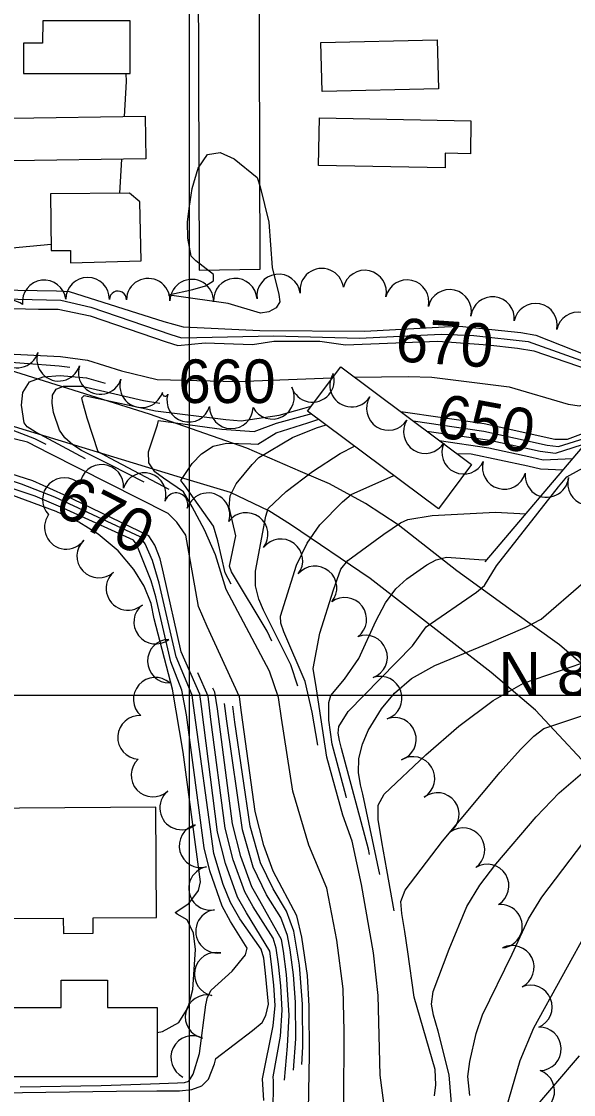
# Model space of a CAD drawing. Extents: x 79600 to 91800, y 75600 to 84400.
# Drawn here: x 84622.9 to 84876.3, y 82816.8 to 83309.4 of the extents above; entities that cross this region are included whole.
import ezdxf

# ---------------------------------------------------------------- set-up
doc = ezdxf.new("R2010")
doc.units = 0
for name, color, linetype in [('084-085$0$BLDG', 7, 'Continuous'), ('084-085$0$GRID', 7, 'Continuous'), ('084-085$0$INDEX', 7, 'Continuous'), ('084-085$0$INDXLBL', 7, 'Continuous'), ('084-085$0$INTER', 7, 'Continuous'), ('084-085$0$ROAD', 7, 'Continuous'), ('084-085$0$TREES', 7, 'Continuous'), ('084-085$0$WALL', 7, 'Continuous'), ('084-090$0$GRID', 7, 'Continuous'), ('084-090$0$TI_BORDER', 7, 'Continuous')]:
    doc.layers.add(name, color=color, linetype=linetype)

msp = doc.modelspace()

# ---------------------------------------------------------------- linework, layer by layer
at = {"layer": '084-085$0$BLDG'}
for points in [[(84632.59, 83299.52), (84623.84, 83299.53), (84623.82, 83285.55), (84672.7, 83285.47), (84672.74, 83309.69), (84632.61, 83309.75)], [(84814.26, 83278.51), (84760.86, 83277.2), (84760.3, 83299.73), (84813.7, 83301.04)], [(84679.96, 83246.32), (84618.56, 83245.4), (84618.27, 83264.98), (84679.67, 83265.9)], [(84828.92, 83248.69), (84817.4, 83248.9), (84817.28, 83242.26), (84759.25, 83243.35), (84759.66, 83265.15), (84829.2, 83263.84)], [(84636.25, 83230.28), (84636.51, 83204.21), (84645.39, 83204.29), (84645.44, 83198.59), (84677.86, 83199.47), (84677.12, 83226.67), (84672.43, 83230.63)], [(84769.42, 83150.92), (84829.42, 83106.08), (84814.23, 83085.75), (84754.23, 83130.59)], [(84580.41, 82897.68), (84604.06, 82897.84), (84604.11, 82890.71), (84617.59, 82890.81), (84617.54, 82897.58), (84642.03, 82897.75), (84642.08, 82890.78), (84655.75, 82890.87), (84655.7, 82897.85), (84684.85, 82898.06), (84684.5, 82948.69), (84580.07, 82947.96)], [(84641.12, 82856.71), (84641.12, 82869.23), (84662.34, 82869.24), (84662.35, 82856.79), (84685.1, 82856.8), (84685.11, 82824.98), (84609.62, 82824.95), (84609.61, 82856.7)]]:
    msp.add_lwpolyline(points, close=True, dxfattribs=at)
at = {"layer": '084-085$0$GRID'}
msp.add_line((85000, 83000), (80000, 83000), dxfattribs=at)
at = {"layer": '084-085$0$INDEX'}
for points in [[(84600.69, 83178.14), (84630.62, 83177.35), (84639.67, 83177.29), (84654.42, 83174.27), (84689.3, 83162.42), (84694.63, 83160.72), (84707.14, 83161.95), (84728.87, 83161.11), (84738.73, 83162.64), (84759.87, 83162.62), (84771.59, 83161), (84814.01, 83162.68), (84836.88, 83160.95), (84850.54, 83159.5), (84858.07, 83158.14), (84887.97, 83147.96)], [(84613.42, 83157.05), (84640.78, 83155.58), (84653.15, 83153.95), (84668.79, 83149.1), (84685.18, 83144.99), (84721.6, 83144.12), (84765.37, 83145.87), (84765.65, 83145.88)], [(84775.93, 83146.06), (84800.37, 83146.48), (84811.16, 83146.11), (84846.77, 83141.61), (84873.75, 83133.74), (84879.07, 83132.94), (84882.6, 83134.05), (84889.03, 83133.81), (84925.64, 83118.29), (84936.16, 83113.35), (84942.47, 83111.34), (84949.29, 83110.42), (84963.52, 83112.56), (84976.14, 83115.96), (84981.44, 83117.59), (84986.28, 83119.78), (85000, 83131.29)], [(84797.03, 83130.29), (84835.27, 83124.87), (84867.74, 83117.7), (84873.5, 83117.68), (84882.14, 83120.89), (84885.57, 83121.36), (84894.14, 83119.08), (84907.07, 83114.28), (84930.3, 83102.42), (84935.65, 83099.95), (84941.32, 83098.68), (84948.66, 83099), (84969.1, 83104.02), (84989.2, 83110.03), (85000, 83117.94)], [(84770.89, 82812.2), (84770.95, 82845.86), (84770.56, 82865.33), (84767.7, 82887.72), (84763.04, 82911.54), (84754.72, 82931.33), (84747.41, 82956.06), (84742.21, 82989.57), (84740.79, 82999.09), (84736.79, 83011.16), (84716.86, 83048.62), (84711.98, 83064.62), (84706.88, 83076.04), (84701.2, 83086.55), (84697.21, 83093.55), (84688.11, 83099.71), (84684.03, 83102.74), (84681.34, 83106.85), (84681.2, 83111.92), (84685.27, 83124.25), (84685.79, 83126.17), (84714.82, 83122.19), (84729.72, 83121.15), (84739.99, 83124.97), (84755.15, 83129.1), (84755.94, 83129.32)], [(84754.44, 82801.21), (84755.14, 82834.95), (84754.98, 82857.36), (84754.16, 82871.43), (84751.62, 82888.97), (84749.33, 82898.8), (84738.41, 82919.37), (84734.16, 82931.14), (84730.15, 82946.66), (84723.88, 82992.22), (84722.87, 82999.42), (84708.08, 83031.7), (84704.11, 83040.89), (84699.29, 83068.36), (84698.3, 83073.53), (84694.25, 83079.59), (84690.23, 83083.46), (84635.72, 83111.09), (84625.56, 83116.31), (84614.94, 83118.89)], [(84734.16, 82814.01), (84733.49, 82824.02), (84738.44, 82848.36), (84739.35, 82857.71), (84738.69, 82867.06), (84737.66, 82876.7), (84736.85, 82882.66), (84726.13, 82900.19), (84722.1, 82907.42), (84716.48, 82922.83), (84712.89, 82937.26), (84705.54, 82994.86), (84704.74, 83000.59), (84696.23, 83020.07), (84688.03, 83056.1), (84686.53, 83062.72), (84684.14, 83069.05), (84681.29, 83073.28), (84642.31, 83092.12), (84628.08, 83098.53), (84618.03, 83101.8)], [(84789.99, 82807.25), (84787.46, 82825.72), (84786.64, 82862.26), (84784.47, 82881.83), (84778.99, 82913.19), (84774.71, 82933.14), (84770.32, 82945.08), (84763.03, 82971.73), (84758.32, 83003.08), (84756.77, 83012.31), (84759.81, 83028.55), (84766.03, 83048.54), (84769.48, 83058), (84772.67, 83061.91), (84789.25, 83074.09), (84796.8, 83079.19), (84800.23, 83080.81), (84811.44, 83082.64), (84840.48, 83084.21), (84854.31, 83083.37)], [(84812.44, 82816.18), (84813.14, 82821.23), (84812.72, 82828.34), (84803.13, 82861.49), (84800.25, 82882.28), (84798.8, 82891.7), (84797.52, 82899.93), (84797.04, 82905.38), (84798.93, 82910.55), (84816.14, 82933.05), (84842.63, 82964.86), (84851.89, 82975.21), (84858.13, 82981.36), (84862.64, 82984.84), (84904.89, 82998.96)]]:
    msp.add_lwpolyline(points, dxfattribs=at)
at = {"layer": '084-085$0$INTER'}
msp.add_line((84668.08, 83230.59), (84668.98, 83246.15), dxfattribs=at)
for points in [[(84670.11, 83265.75), (84671.04, 83281.83), (84670.96, 83285.47)], [(84453.38, 83232.93), (84461.75, 83230.58), (84475.08, 83222.88), (84480.65, 83219.56), (84532.34, 83204.8), (84540.51, 83203.1), (84555.44, 83201.56), (84570.31, 83200.91), (84626.75, 83206.24), (84636.48, 83207.12)], [(84399.8, 83133.35), (84399.48, 83133.66), (84396.09, 83136.82), (84401.25, 83144.46), (84411.96, 83173.61), (84414.41, 83181.53), (84415.26, 83183.72), (84418.13, 83186.19), (84438.41, 83189.33), (84534.13, 83190.88), (84561.82, 83190.24), (84594.28, 83186.5), (84638.9, 83185.76), (84644.74, 83185.39), (84688.16, 83171.72), (84697.11, 83169.26), (84732.33, 83167.57), (84780.5, 83167.18), (84817.11, 83169.16), (84823.94, 83169.5), (84852.04, 83166.65), (84859.01, 83165.47), (84882.18, 83156.19)], [(84436.19, 83127.82), (84428.13, 83136.47), (84427.4, 83147.43), (84427.72, 83154.33), (84430.17, 83166.84), (84433.23, 83177.63), (84435.64, 83180.52), (84442.38, 83182.23), (84528.29, 83186.73), (84549.58, 83186.91), (84594.73, 83182.62), (84640.9, 83181.53), (84654.66, 83178.33), (84691.41, 83165.78), (84696.3, 83164.22), (84738.48, 83165.14), (84777.96, 83163.96), (84815.56, 83165.92), (84830.45, 83165.23), (84855.49, 83162.54), (84888.55, 83150.67)], [(84634.16, 83115.18), (84628.97, 83117.84), (84619.05, 83121.6), (84611.39, 83124.97), (84606.27, 83128.02), (84601.94, 83131.63), (84599.33, 83135.53), (84598.01, 83139.6), (84596.33, 83147.77), (84596.27, 83151.2), (84598.08, 83153.46), (84607.93, 83153.83), (84640.21, 83151.32), (84645.01, 83150.78)], [(84652.25, 83108.68), (84629.17, 83121.01), (84625.54, 83123.26), (84624.03, 83125.18), (84622.95, 83133.31), (84623.53, 83139.15), (84626.54, 83143.95), (84632.78, 83146.35), (84640.63, 83146.86), (84652.77, 83145.81), (84661.34, 83143.43)], [(84679.15, 83097.97), (84663.81, 83105.66), (84650.4, 83112.5), (84646.41, 83115.11), (84642.81, 83118.26), (84640.27, 83121.85), (84637.58, 83129.93), (84636.9, 83134.14), (84637.07, 83137.91), (84638.73, 83140.66), (84642.22, 83142), (84650.63, 83142.03), (84678.91, 83135.44), (84686.39, 83134.13)], [(84690.59, 83094.51), (84663.7, 83108.73), (84658.08, 83111.84), (84652.99, 83127.26), (84650.81, 83135.09), (84650.61, 83136.68), (84651.65, 83137.65), (84684.35, 83130.64), (84716.65, 83126.74), (84723.75, 83126.13), (84741.11, 83128.7), (84752.61, 83131.95), (84755.87, 83132.78)], [(84719.06, 83051.08), (84716.35, 83056.33), (84713, 83071.03), (84711, 83077.66), (84697.72, 83096.56), (84696.05, 83098.63), (84701.29, 83106.45), (84705.52, 83110.9), (84710.88, 83114.39), (84717.05, 83115.87), (84728.19, 83115.5), (84731.38, 83115.44), (84739.82, 83120.51), (84754.28, 83125.17), (84759.29, 83126.81)], [(84802.64, 83126.1), (84835.11, 83121.27), (84864.12, 83114.94), (84869.31, 83114.36), (84881.56, 83118.19), (84884.87, 83118.87), (84892.63, 83117.1), (84910.77, 83110.14), (84930.26, 83099.74), (84935.55, 83097.27), (84941.09, 83096.15), (84948.53, 83096.72), (84970.21, 83102.31), (84986.78, 83107.29), (84993.3, 83109.65), (85000, 83115.27)], [(84737.75, 83024.98), (84735.66, 83029.5), (84719.35, 83056.73), (84718.32, 83059.29), (84721.24, 83073.22), (84718.18, 83086.47), (84718.73, 83091.7), (84721.44, 83097.15), (84728.79, 83106.07), (84731.82, 83109.32), (84747.3, 83118.48), (84758.22, 83122.79), (84762.7, 83124.26)], [(84808.95, 83121.38), (84837.86, 83117.25), (84860.92, 83112.12), (84868.06, 83111.25), (84884.18, 83116.38), (84891.12, 83115.12), (84903.78, 83110.63), (84930.22, 83097.06), (84935.45, 83094.59), (84940.86, 83093.62), (84948.41, 83094.44), (84971.33, 83100.61), (84988.56, 83105.85), (84994.47, 83107.97), (85000, 83112.6)], [(84814.65, 83117.12), (84837.33, 83113.67), (84857.15, 83109.34), (84862.28, 83108.21), (84875.86, 83108.75)], [(84749.75, 83004.27), (84746.5, 83014.08), (84734.02, 83039.2), (84731.79, 83044.19), (84730.32, 83050.26), (84730.27, 83057), (84734.97, 83082.25), (84736.15, 83085.77), (84744.37, 83093.64), (84756.4, 83102.79), (84769.21, 83111.1), (84775.77, 83114.5)], [(84822.77, 83111.05), (84829.24, 83110.98), (84855.34, 83105.47), (84861.06, 83103.99), (84871.51, 83103.63)], [(84758.88, 82977.24), (84756.28, 82992.4), (84753.04, 83006.42), (84743.36, 83029.26), (84741.86, 83033.14), (84741.81, 83036.33), (84749.18, 83059.75), (84754, 83069.96), (84759.8, 83078.37), (84770.29, 83088.91), (84774.23, 83092.22), (84793.78, 83101.03)], [(84782.67, 82926.95), (84782.22, 82929.37), (84769.83, 82975.6), (84768.83, 82979.29), (84768.21, 82982.69), (84768.6, 82985.77), (84772.79, 82992.66), (84802.33, 83022.85), (84808.69, 83031.44), (84831.71, 83047.45), (84835.35, 83050.47), (84840.88, 83059.54), (84869.41, 83095.73), (84873.16, 83100.34), (84879.09, 83103.64), (84882.22, 83105.24), (84889.67, 83103.56), (84903.38, 83098.11), (84930.01, 83083.64), (84934.88, 83081.17), (84939.17, 83080.79), (84982.25, 83093.32), (85000, 83096.88)], [(84612.32, 82817.59), (84666.43, 82818.35), (84684.97, 82818.46), (84695.46, 82818.55), (84701.01, 82819.09), (84705.66, 82820.77), (84708.75, 82823.92), (84711.42, 82830.88), (84712.03, 82833.39), (84728.84, 82846.26), (84733.37, 82849.86), (84735.1, 82853.08), (84736.24, 82858.36), (84734.95, 82872.45), (84734.16, 82879.47), (84732.88, 82883.52), (84723.08, 82897.43), (84718.83, 82905.02), (84715.43, 82913.28), (84711.24, 82927.5), (84701.88, 82995.39), (84701.29, 83000.17), (84693.86, 83017.75), (84686.11, 83051.53), (84682.95, 83061.9), (84679.59, 83069.62), (84677.42, 83072.79), (84638.12, 83091.02), (84622.92, 83097.03), (84617.89, 83098.63)], [(84622.32, 82820.34), (84659.51, 82821.01), (84682.13, 82821.69), (84694.54, 82822.1), (84697.75, 82822.35), (84699.68, 82823), (84701.71, 82826.18), (84704.63, 82835.7), (84707.54, 82857.99), (84708.25, 82861.51), (84709.88, 82864.7), (84719.62, 82873.49), (84725.69, 82880.92), (84726.5, 82884.03), (84718.77, 82896.25), (84715.02, 82903.33), (84709.38, 82919.53), (84706.66, 82930.02), (84698.66, 82991.08), (84696.48, 83002.45), (84691.48, 83015.45), (84684.49, 83045.29), (84682.46, 83052.61), (84676.64, 83067.09), (84675.54, 83069.62), (84674.34, 83071.34), (84642.06, 83086.06), (84629.12, 83091.43), (84614.39, 83096.4)], [(84685.1, 82845.32), (84687.64, 82845.76), (84695.04, 82849.92), (84699.44, 82856.81), (84701.53, 82865.06), (84702.78, 82883.39), (84701.88, 82890.92), (84698.91, 82896.94), (84694.33, 82899.58), (84693.39, 82900.33), (84699.64, 82904.53), (84704.12, 82910.49), (84705.1, 82914.51), (84697.14, 82973.91), (84692.24, 83002.85), (84683.76, 83035.25), (84682.33, 83042.27), (84679.21, 83050.15), (84674.5, 83057.79), (84667.2, 83066.37), (84658.05, 83074.02), (84649.16, 83079.53), (84638.77, 83084.4), (84617.63, 83092.27)], [(84793.9, 82901.09), (84790.55, 82919.92), (84788.21, 82932.88), (84786.65, 82943.12), (84786.59, 82949.59), (84789.35, 82954.69), (84808.46, 82972.82), (84823.66, 82985.87), (84839.35, 82997.65), (84853.28, 83005.64), (84880.14, 83014.83), (84923.29, 83043.44), (84936.9, 83053.27), (84945.21, 83060.12), (84950.04, 83064.21), (84954.5, 83066.36), (84983.38, 83066.72), (84988.87, 83066.64), (84993.09, 83067.35), (84996.07, 83069.11), (85000, 83074.9)], [(84772.07, 82953.06), (84771.9, 82953.62), (84765.42, 82977.63), (84763.99, 82988.73), (84764.02, 82996.84), (84764.89, 82999.94), (84771.18, 83007.48), (84777.71, 83017.04), (84785.5, 83034.17), (84789.95, 83042.55), (84794.78, 83048.91), (84799.74, 83053.52), (84808.9, 83059.97), (84813.23, 83062.2), (84817.94, 83063.43), (84832.76, 83062.4), (84836.39, 83062.25)], [(84787.4, 82917.75), (84779.59, 82954.69), (84778.5, 82959), (84777.62, 82964.67), (84777.72, 82971.08), (84779.34, 82977.63), (84782.03, 82983.87), (84788.09, 82993.86), (84794.14, 83001.03), (84801.83, 83007.82), (84812.55, 83013.79), (84837.35, 83023.97), (84854.1, 83031.23), (84861.5, 83035.09), (84880.88, 83051.92)], [(84681.63, 82775.31), (84715.84, 82787.01), (84729.35, 82792.41), (84736.1, 82799.16), (84738.35, 82808.16), (84738.57, 82823.02), (84738.47, 82824.85), (84741.73, 82843.64), (84742.51, 82855.49), (84741.88, 82866.75), (84740.85, 82876.58), (84739.8, 82883.92), (84738.37, 82888.61), (84729.18, 82902.95), (84725.36, 82909.81), (84720.01, 82924.49), (84716.34, 82939.14), (84709.83, 82988.9), (84708.53, 82999.69), (84703.84, 83010.41)], [(84743.64, 82823.47), (84745.03, 82838.93), (84745.67, 82853.26), (84744.56, 82871.94), (84743.19, 82882.66), (84742.18, 82887.93), (84732.23, 82905.71), (84728.62, 82912.2), (84723.55, 82926.15), (84719.79, 82941.02), (84712.88, 82993.8), (84711.63, 83001.44), (84710.76, 83003.35)], [(84747.69, 82827.97), (84748.75, 82842.38), (84748.64, 82859.22), (84747.76, 82871.77), (84746.25, 82883.29), (84745.01, 82889.87), (84741.85, 82898.04), (84735.29, 82908.46), (84729.16, 82921.23), (84724.29, 82938.36), (84717.12, 82988.15), (84716.1, 82996.37)], [(84751.53, 82830.61), (84751.95, 82838.67), (84751.81, 82858.29), (84750.42, 82876.22), (84747.85, 82891.81), (84744.59, 82900.97), (84738.34, 82911.22), (84732.59, 82923.22), (84727.81, 82940.03), (84720.77, 82987.78), (84719.84, 82995.1)], [(84820.59, 82808.82), (84819.21, 82825.89), (84814.13, 82845.92), (84812.07, 82853.19), (84811.1, 82858.27), (84811.81, 82864.12), (84819.19, 82883.6), (84827.36, 82903.19), (84833.33, 82912.88), (84840.66, 82922.57), (84859.18, 82944.24), (84869.75, 82955.27), (84880.41, 82964.44)], [(84828.63, 82816.32), (84827.7, 82825.06), (84828.68, 82831.95), (84831.56, 82844.88), (84834.52, 82853.45), (84848.18, 82881.23), (84855.66, 82897.41), (84861.67, 82907.35), (84880.95, 82932.75)], [(84845.47, 82810.79), (84851.76, 82832.42), (84858.02, 82847.49), (84884.01, 82894.49)], [(84843.69, 82793.19), (84879.09, 82834.53)]]:
    msp.add_lwpolyline(points, dxfattribs=at)
msp.add_lwpolyline([(84732.49, 83233.55), (84736.4, 83217.34), (84737.93, 83196.4), (84741.06, 83184.1), (84741.4, 83180.76), (84739.71, 83177.98), (84736.48, 83176.1), (84732.52, 83175.48), (84717.74, 83180), (84692.92, 83183.4), (84691.47, 83183.58), (84690.28, 83183.87), (84701.5, 83186.3), (84707.31, 83188.06), (84711.05, 83190.39), (84711.02, 83193.2), (84702.91, 83199.49), (84700.74, 83201.64), (84699.3, 83209.96), (84699.12, 83217.23), (84699.77, 83223.61), (84701.26, 83232.76), (84703.95, 83242.13), (84708.22, 83248.38), (84714.14, 83249.2), (84720.52, 83246.38), (84730.99, 83237.77)], close=True, dxfattribs=at)
at = {"layer": '084-085$0$ROAD'}
for points in [[(84703.03, 83604.4), (84704.45, 83195.29), (84732.39, 83195.72), (84731.28, 83605.45)], [(84890.82, 82958.91), (84858.83, 82993.18), (84838.43, 83010.57), (84782.89, 83053.72), (84746.36, 83078.52), (84736.42, 83084.75), (84718.74, 83093.22), (84694.27, 83100.55), (84541.28, 83147.2), (84521.48, 83150.87), (84494.3, 83151.68), (84347.63, 83152.24), (84340.7, 83149.7), (84335.97, 83144.4), (84332.98, 83135.11), (84333.85, 82984.13), (84334.03, 82747.45)], [(84887.24, 83008.28), (84869.8, 83023.24), (84848.34, 83038.77), (84822.69, 83057.2), (84795.77, 83078.39), (84780.85, 83088.12), (84764.24, 83097.22), (84750.91, 83102.8), (84726.26, 83113.52), (84681.64, 83129.14), (84617.37, 83149.34)]]:
    msp.add_lwpolyline(points, dxfattribs=at)
at = {"layer": '084-085$0$TREES'}
for centre, radius, start, end in [((84760.73, 83186.04), 10, 7.6622, 187.6622), ((84780.39, 83185.17), 10, 347.2722, 167.2722), ((84633.3, 83180.69), 10, 7.0171, 187.0171), ((84653.23, 83181.88), 10, 359.8244, 179.8244), ((84681.04, 83181.45), 10, 358.7118, 178.7118), ((84701.03, 83181), 10, 358.7118, 178.7118), ((84721.01, 83181.44), 10, 3.8278, 183.8278), ((84740.9, 83183.41), 10, 7.4662, 187.4662), ((84799.9, 83180.77), 10, 347.2719, 167.2719), ((84667.13, 83181.76), 3.91, 358.7118, 178.7118), ((84819.4, 83176.32), 10, 347.0108, 167.0108), ((84617.37, 83171.47), 10, 53.0824, 233.0824), ((84839.09, 83173.01), 10, 353.9103, 173.9103), ((84858.83, 83169.97), 10, 348.5942, 168.5942), ((84878.43, 83165.98), 10, 348.37, 168.37), ((84620.89, 83160.43), 10, 162.2585, 342.2585), ((84639.94, 83154.34), 10, 162.2585, 342.2585), ((84658.99, 83148.24), 10, 162.2585, 342.2585), ((84678.03, 83142.15), 10, 162.2585, 342.2585), ((84756.44, 83144.66), 10, 198.3648, 18.3648), ((84774.38, 83142.48), 10, 147.7373, 327.7373), ((84738.08, 83136.88), 10, 207.607, 27.607), ((84688.79, 83138.71), 1.29, 162.2585, 342.2585), ((84699.63, 83135.52), 10, 163.7843, 343.7843), ((84791.28, 83131.77), 10, 147.5284, 327.5284), ((84719.23, 83132.49), 10, 178.6185, 358.6185), ((84808.22, 83121.15), 10, 148.3358, 328.3358), ((84825.8, 83111.67), 10, 154.9942, 334.9942), ((84659.71, 83096.02), 10, 355.0952, 175.0952), ((84844.48, 83104.71), 10, 164.1151, 344.1151), ((84679.22, 83092.2), 10, 342.7255, 162.7255), ((84864.05, 83101), 10, 174.3944, 354.3944), ((84642.54, 83089.95), 10, 43.8612, 223.8612), ((84883.61, 83097.25), 10, 163.905, 343.905), ((84693.88, 83087.61), 5.36, 342.3968, 162.3968), ((84708.51, 83082.96), 10, 342.3968, 162.3968), ((84643.43, 83077.16), 10, 144.1537, 324.1537), ((84726.02, 83073.9), 10, 322.8703, 142.8703), ((84658.33, 83063.97), 10, 132.816, 312.816), ((84741.96, 83061.83), 10, 322.8667, 142.8667), ((84671.74, 83049.13), 10, 131.3696, 311.3696), ((84757.61, 83049.38), 10, 320.152, 140.152), ((84684.44, 83033.69), 10, 127.5046, 307.5046), ((84771.29, 83034.98), 10, 306.8667, 126.8667), ((84780.83, 83017.63), 10, 290.7682, 110.7682), ((84690.71, 83015.76), 10, 91.0582, 271.0582), ((84684.28, 82998.26), 10, 48.6018, 228.6018), ((84787.56, 82998.79), 10, 288.5384, 108.5384), ((84677.05, 82980.78), 10, 86.4371, 266.4371), ((84794.06, 82979.88), 10, 289.3908, 109.3908), ((84683.22, 82963.46), 10, 132.8128, 312.8128), ((84802.57, 82961.9), 10, 301.2545, 121.2545), ((84696.34, 82948.38), 10, 129.2256, 309.2256), ((84813.75, 82945.35), 10, 306.8509, 126.8509), ((84705.24, 82930.97), 10, 104.9405, 284.9405), ((84825.57, 82929.21), 10, 305.5767, 125.5767), ((84709.62, 82911.47), 10, 100.3555, 280.3555), ((84836.62, 82912.56), 10, 301.5276, 121.5276), ((84842.77, 82894.07), 10, 275.3126, 95.3126), ((84712.87, 82891.74), 10, 98.3484, 278.3484), ((84848.17, 82875.18), 10, 296.6075, 116.6075), ((84712.26, 82872.06), 10, 78.126, 258.126), ((84856.47, 82856.99), 10, 292.4214, 112.4214), ((84708.06, 82852.51), 10, 77.6198, 257.6198), ((84860.63, 82837.75), 10, 271.9997, 91.9997), ((84701.46, 82833.79), 10, 63.5176, 243.5176), ((84857.58, 82818.36), 10, 250.0948, 70.0948)]:
    msp.add_arc(centre, radius, start, end, dxfattribs=at)
at = {"layer": '084-085$0$WALL'}
msp.add_line((84882.92, 83117.08), (84835.62, 83061.34), dxfattribs=at)
at = {"layer": '084-090$0$TI_BORDER'}
msp.add_lwpolyline([(84700, 84300), (91700, 84300), (91700, 79700), (84700, 79700)], close=True, dxfattribs=at)

# ---------------------------------------------------------------- texts
at = {"layer": '084-085$0$INDXLBL'}
for s, rotation, p in [('670', 356.123, (84794.19, 83153.47)), ('650', 349.5666, (84812.34, 83119.06)), ('670', 333.1031, (84636.93, 83084.12))]:
    msp.add_text(s, height=20, rotation=rotation, dxfattribs=at).set_placement(p)
msp.add_text('660', height=20, dxfattribs=at).set_placement((84694.88, 83134.26))
at = {"layer": '084-090$0$GRID'}
msp.add_text('N 83,000', height=20, dxfattribs=at).set_placement((84841.9, 83000))

doc.saveas('drawing.dxf')
